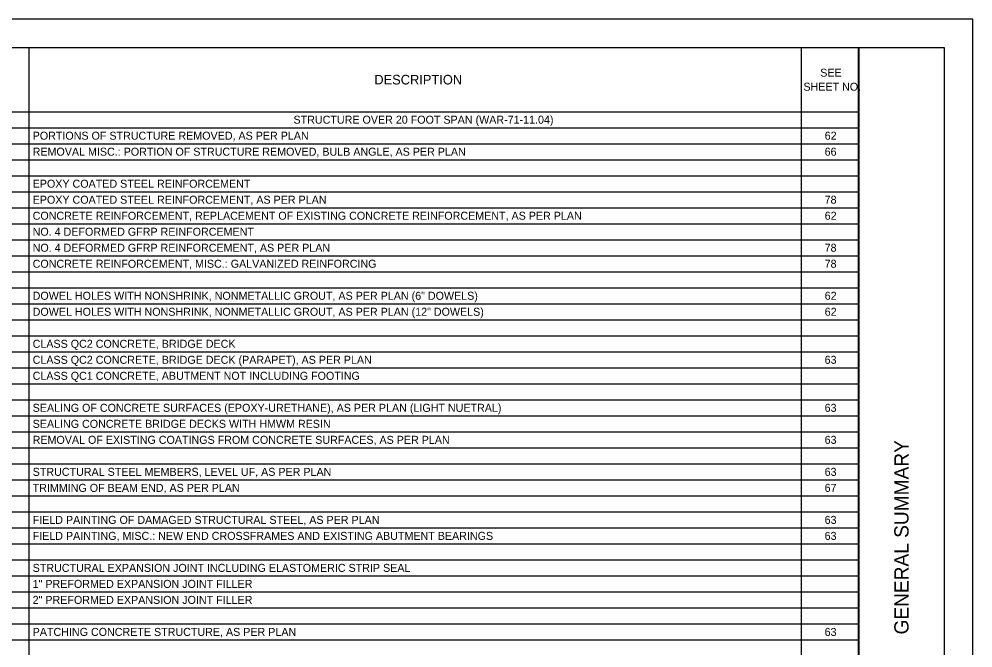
# Model space of a CAD drawing. Extents: x 0 to 34, y 0 to 22.
# Drawn here: x 17.32 to 34, y 11 to 22 of the extents above; entities that cross this region are included whole.
import ezdxf

# ---------------------------------------------------------------- set-up
doc = ezdxf.new("R2010")
doc.units = 0
for name, color, linetype in [('Default', 7, 'Continuous'), ('SH_Border', 7, 'Continuous'), ('SH_Cut_Line', 7, 'Continuous'), ('SH_Data', 7, 'Continuous')]:
    doc.layers.add(name, color=color, linetype=linetype)

msp = doc.modelspace()

# ---------------------------------------------------------------- linework, layer by layer
at = {"layer": 'Default'}
for p, q in [((1.5, 21.5), (32.004, 21.5)), ((17.493, 21.5), (17.493, 0.5)), ((30.999, 21.5), (30.999, 0.5)), ((32.004, 21.5), (32.004, 0.5)), ((1.5, 20.38), (32.004, 20.38)), ((1.5, 20.1), (32.004, 20.1)), ((1.5, 19.82), (32.004, 19.82)), ((1.5, 19.54), (32.004, 19.54)), ((1.5, 19.26), (32.004, 19.26)), ((1.5, 18.98), (32.004, 18.98)), ((1.5, 18.7), (32.004, 18.7)), ((1.5, 18.42), (32.004, 18.42)), ((1.5, 18.14), (32.004, 18.14)), ((1.5, 17.86), (32.004, 17.86)), ((1.5, 17.58), (32.004, 17.58)), ((1.5, 17.3), (32.004, 17.3)), ((1.5, 17.02), (32.004, 17.02)), ((1.5, 16.74), (32.004, 16.74)), ((1.5, 16.46), (32.004, 16.46)), ((1.5, 16.18), (32.004, 16.18)), ((1.5, 15.9), (32.004, 15.9)), ((1.5, 15.62), (32.004, 15.62)), ((1.5, 15.34), (32.004, 15.34)), ((1.5, 15.06), (32.004, 15.06)), ((1.5, 14.78), (32.004, 14.78)), ((1.5, 14.5), (32.004, 14.5)), ((1.5, 14.22), (32.004, 14.22)), ((1.5, 13.94), (32.004, 13.94)), ((1.5, 13.66), (32.004, 13.66)), ((1.5, 13.38), (32.004, 13.38)), ((1.5, 13.1), (32.004, 13.1)), ((1.5, 12.82), (32.004, 12.82)), ((1.5, 12.54), (32.004, 12.54)), ((1.5, 12.26), (32.004, 12.26)), ((1.5, 11.98), (32.004, 11.98)), ((1.5, 11.7), (32.004, 11.7)), ((1.5, 11.42), (32.004, 11.42)), ((1.5, 11.14), (32.004, 11.14))]:
    msp.add_line(p, q, dxfattribs=at)
at = {"layer": 'SH_Border'}
msp.add_line((32, 0.5), (32, 21.5), dxfattribs=at)
msp.add_lwpolyline([(1.5, 21.5), (33.5, 21.5), (33.5, 0.5), (1.5, 0.5)], close=True, dxfattribs=at)
at = {"layer": 'SH_Cut_Line'}
msp.add_lwpolyline([(0, 0), (34, 0), (34, 22), (0, 22)], close=True, dxfattribs=at)

# ---------------------------------------------------------------- texts
at = {"layer": 'Default'}
for s, height, p in [('DESCRIPTION', 0.168, (23.533, 20.856)), ('SEE ', 0.14, (31.33, 20.992)), ('SHEET NO.', 0.14, (31.036, 20.747)), ('STRUCTURE OVER 20 FOOT SPAN (WAR-71-11.04)', 0.14, (22.12, 20.17)), ('PORTIONS OF STRUCTURE REMOVED, AS PER PLAN', 0.14, (17.559, 19.89)), ('62', 0.14, (31.408, 19.89)), ('REMOVAL MISC.: PORTION OF STRUCTURE REMOVED, BULB ANGLE, AS PER PLAN', 0.14, (17.559, 19.61)), ('66', 0.14, (31.407, 19.61)), ('EPOXY COATED STEEL REINFORCEMENT', 0.14, (17.559, 19.05)), ('EPOXY COATED STEEL REINFORCEMENT, AS PER PLAN', 0.14, (17.559, 18.77)), ('78', 0.14, (31.407, 18.77)), ('CONCRETE REINFORCEMENT, REPLACEMENT OF EXISTING CONCRETE REINFORCEMENT, AS PER PLAN', 0.14, (17.559, 18.49)), ('62', 0.14, (31.408, 18.49)), ('NO. 4 DEFORMED GFRP REINFORCEMENT', 0.14, (17.559, 18.21)), ('NO. 4 DEFORMED GFRP REINFORCEMENT, AS PER PLAN', 0.14, (17.559, 17.93)), ('78', 0.14, (31.407, 17.93)), ('CONCRETE REINFORCEMENT, MISC.: GALVANIZED REINFORCING', 0.14, (17.559, 17.65)), ('78', 0.14, (31.407, 17.65)), ('DOWEL HOLES WITH NONSHRINK, NONMETALLIC GROUT, AS PER PLAN (6" DOWELS)', 0.14, (17.559, 17.09)), ('62', 0.14, (31.408, 17.09)), ('DOWEL HOLES WITH NONSHRINK, NONMETALLIC GROUT, AS PER PLAN (12" DOWELS)', 0.14, (17.559, 16.81)), ('62', 0.14, (31.408, 16.81)), ('CLASS QC2 CONCRETE, BRIDGE DECK', 0.14, (17.559, 16.25)), ('CLASS QC2 CONCRETE, BRIDGE DECK (PARAPET), AS PER PLAN', 0.14, (17.559, 15.97)), ('63', 0.14, (31.407, 15.97)), ('CLASS QC1 CONCRETE, ABUTMENT NOT INCLUDING FOOTING', 0.14, (17.559, 15.69)), ('SEALING OF CONCRETE SURFACES (EPOXY-URETHANE), AS PER PLAN (LIGHT NUETRAL)', 0.14, (17.559, 15.13)), ('63', 0.14, (31.407, 15.13)), ('SEALING CONCRETE BRIDGE DECKS WITH HMWM RESIN', 0.14, (17.559, 14.85)), ('REMOVAL OF EXISTING COATINGS FROM CONCRETE SURFACES, AS PER PLAN', 0.14, (17.559, 14.57)), ('63', 0.14, (31.407, 14.57)), ('STRUCTURAL STEEL MEMBERS, LEVEL UF, AS PER PLAN', 0.14, (17.559, 14.01)), ('63', 0.14, (31.407, 14.01)), ('TRIMMING OF BEAM END, AS PER PLAN', 0.14, (17.559, 13.73)), ('67', 0.14, (31.407, 13.73)), ('FIELD PAINTING OF DAMAGED STRUCTURAL STEEL, AS PER PLAN', 0.14, (17.559, 13.17)), ('63', 0.14, (31.407, 13.17)), ('FIELD PAINTING, MISC.: NEW END CROSSFRAMES AND EXISTING ABUTMENT BEARINGS', 0.14, (17.559, 12.89)), ('63', 0.14, (31.407, 12.89)), ('STRUCTURAL EXPANSION JOINT INCLUDING ELASTOMERIC STRIP SEAL', 0.14, (17.559, 12.33)), ('1" PREFORMED EXPANSION JOINT FILLER', 0.14, (17.559, 12.05)), ('2" PREFORMED EXPANSION JOINT FILLER', 0.14, (17.559, 11.77)), ('PATCHING CONCRETE STRUCTURE, AS PER PLAN', 0.14, (17.559, 11.21)), ('63', 0.14, (31.407, 11.21))]:
    msp.add_text(s, height=height, dxfattribs=at).set_placement(p)
at = {"layer": 'SH_Data'}
msp.add_text('GENERAL SUMMARY', height=0.25, rotation=90, dxfattribs=at).set_placement((32.875, 11.235))

doc.saveas('drawing.dxf')
